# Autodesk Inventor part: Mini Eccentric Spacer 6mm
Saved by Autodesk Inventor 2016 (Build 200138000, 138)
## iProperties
Created: 2015-11
Part Number: Mini Eccentric Spacer 6mm
Material: Generic
Document SubType Name: Modeling
Designer: John
Density: 1 g/cm^3
Appearance: Default
Author: John
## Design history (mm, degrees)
feature "SOLID1"
body "Solid1"
